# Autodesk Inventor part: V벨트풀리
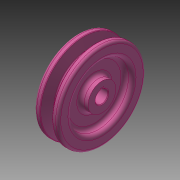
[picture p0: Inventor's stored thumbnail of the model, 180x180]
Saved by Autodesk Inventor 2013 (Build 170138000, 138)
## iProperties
Created: 2015-11
Part Number: V벨트풀리
Material: 강철, 탄소
Document SubType Name: Modeling
Designer: mduedu
Density: 1 g/cm^3
Author: mduedu
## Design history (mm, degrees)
sketch "스케치1"
  geometry: L1 (-9.5, 0)-(9.5, 0); L2 (0, 0)-(0, 34.7); L3 (-4.825, 34.7)-(-9.5, 34.7); L4 (-9.5, 34.7)-(-9.5, 0); L5 (0, 25.7)-(-2.074, 25.7); L6 (-2.074, 25.7)-(-4.825, 34.7); L7 (4.825, 34.7)-(9.5, 34.7); L8 (9.5, 34.7)-(9.5, 0); L9 (0, 25.7)-(2.074, 25.7); L10 (2.074, 25.7)-(4.825, 34.7); L11 (-9.5, 32)-(9.5, 32); 3 further points
  constraints: 22 end point, 7 point on line, 4 perpendicular, 3 symmetric about line, 1 coincident, 1 horizontal, 1 horizontal alignment, 1 midpoint, 1 vertical
  dimensions: "d0" = 19 distance of L1.start L1.end; "d2" = 69.4 diameter of L2.end L1 (derived); "d3" = 34 deg angle of L10 L6; "d4" = 6.3 distance between parallel lines of L11 L9; "d5" = 2.7 distance between parallel lines of L7 L11; "d6" = 8 distance of point (4, 32) point (-4, 32); "d7" = 64 diameter of L11 L1
revolve "회전1" sketch "스케치1" stored, may be unused: angle "d8" = 90 deg
sketch "스케치2"
  geometry: C1 r 24 at (0, 0); C2 r 11 at (0, 0); 1 further point
  constraints: 2 centre point, 2 coincident
  dimensions: "d9" = 48 diameter of C1; "d10" = 22 diameter of C2
extrude "돌출1" cut sketch "스케치2" distance "d11" = 6; taper "d12" = 0 deg
fillet "모깎기1" dims "d13" = 3
fillet "모깎기2" dims "d14" = 3
fillet "모깎기3" dims "d15" = 1, "d16" = 0.5, "d17" = 2
hole "구멍1" diameter "d20" = 10; stored, may be unused: countersink angle "d24" = 90 deg, drill point angle "d26" = 118 deg; dims "d18" = 10, "d19" = 10, "d21" = 6, "d22" = 4, "d23" = 2, "d25" = 8
sketch "스케치3"
  geometry: L1 (-1.5, 0)-(1.5, 0); L2 (1.5, 0)-(1.5, 6.4); L3 (1.5, 6.4)-(-1.5, 6.4); L4 (-1.5, 6.4)-(-1.5, 0); 2 further points
  constraints: 8 end point, 2 parallel, 1 coincident, 1 horizontal, 1 midpoint, 1 perpendicular
  dimensions: "d27" = 3 distance of L2.end L3.end; "d29" = 6.4 distance of L3.end L1.start
extrude "돌출2" cut sketch "스케치3" stored distance "d30" = 6; taper "d31" = 0 deg
chamfer "모따기1" distance "d32" = 0.5; stored, may be unused: second distance "d33" = 2, angle "d34" = 45 deg
node "솔리드1"
mirror "대칭1"
